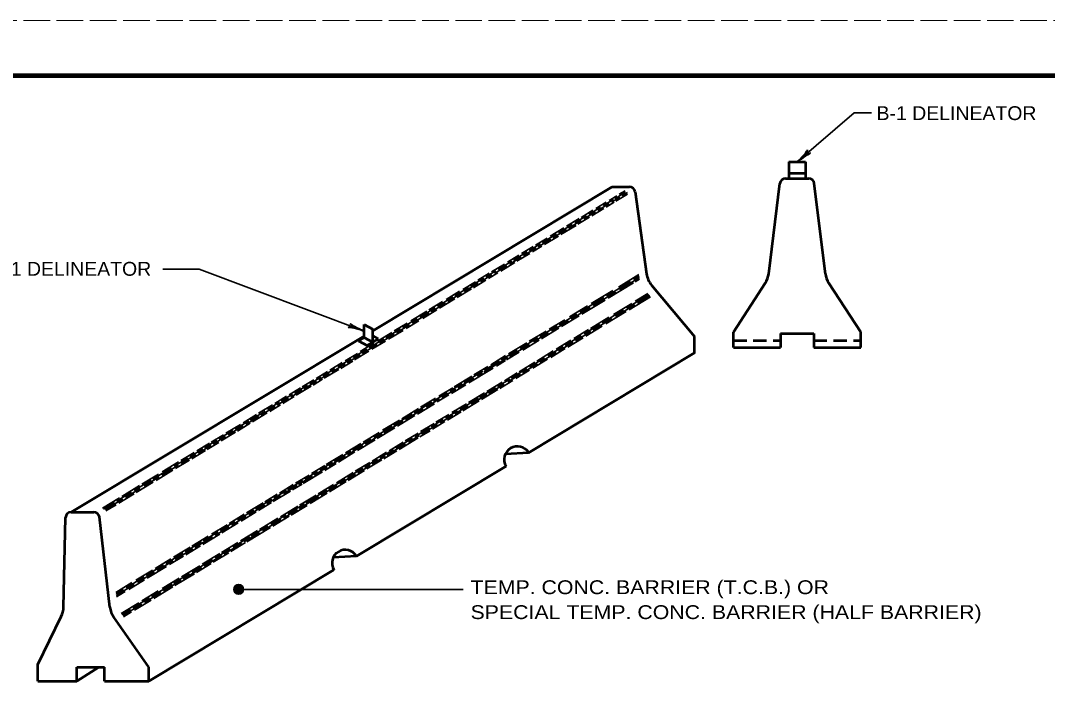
# Model space of a CAD drawing. Extents: x -60 to 620, y -42 to 398.
# Drawn here: x 155.3 to 340.7, y 276.6 to 398.3 of the extents above; entities that cross this region are included whole.
import ezdxf

# ---------------------------------------------------------------- set-up
doc = ezdxf.new("R2010")
doc.units = 0
doc.header["$LTSCALE"] = 0.8
doc.linetypes.add('LONG_DASHED', pattern=[7.5, 6, -1.5])
doc.linetypes.add('MEDIUM_DASHED', pattern=[4.5, 3, -1.5])
doc.layers.add('1', color=7, linetype='Continuous', lineweight=35)
doc.layers.add('61', color=7, linetype='Continuous', lineweight=35)

msp = doc.modelspace()

# ---------------------------------------------------------------- hatches: boundary and pattern name
at = {"layer": '1'}
msp.add_hatch(color=256, dxfattribs=at).paths.add_polyline_path([(195.5118, 295.5681, 1), (193.7618, 295.5681, 1)])

# ---------------------------------------------------------------- linework, layer by layer
for p, q in [((295.478, 372.7356), (305.7999, 381.5928)), ((305.7999, 381.5928), (308.9546, 381.5928)), ((262.5535, 366.1046), (264.5031, 367.2884)), ((263.3894, 366.9047), (264.4197, 367.5302)), ((263.9162, 366.6396), (264.8951, 367.2339)), ((259.1647, 364.3393), (261.0014, 365.4547)), ((260.4839, 364.8479), (262.3297, 365.9687)), ((260.9856, 364.5675), (262.4392, 365.4502)), ((261.5572, 365.7921), (262.9602, 366.644)), ((261.969, 365.4572), (263.4574, 366.361)), ((262.753, 365.6407), (264.8434, 366.9101)), ((256.4974, 362.7197), (258.6156, 364.0059)), ((256.9967, 362.4379), (259.0848, 363.7058)), ((257.872, 363.2619), (260.0132, 364.5621)), ((258.4358, 363.0192), (260.5839, 364.3236)), ((259.505, 363.961), (261.5747, 365.2177)), ((253.8622, 361.1196), (256.1582, 362.5138)), ((254.221, 360.7525), (256.5235, 362.1506)), ((255.3568, 361.7346), (257.4518, 363.0068)), ((255.9095, 361.4853), (258.0276, 362.7714)), ((250.8938, 359.3171), (253.387, 360.831)), ((251.4117, 359.0467), (253.8287, 360.5143)), ((252.3987, 359.9384), (254.8791, 361.4445)), ((252.8405, 359.6217), (255.5677, 361.2777)), ((247.1182, 356.7321), (249.1432, 357.9617)), ((248.2676, 357.7223), (250.3784, 359.0041)), ((248.7187, 357.4115), (251.0367, 358.819)), ((249.4825, 358.1677), (252.0295, 359.7142)), ((249.8741, 357.8205), (252.3858, 359.3457)), ((244.285, 355.0117), (246.737, 356.5006)), ((244.888, 354.7928), (247.2346, 356.2177)), ((245.7516, 356.1946), (247.8228, 357.4522)), ((246.0662, 355.8009), (248.3838, 357.2082)), ((247.7393, 356.5242), (249.4137, 357.5409)), ((240.3007, 352.8847), (242.6382, 354.3041)), ((241.4888, 353.3137), (244.0006, 354.8389)), ((241.975, 353.024), (244.531, 354.5761)), ((243.1803, 354.6332), (245.2448, 355.8869)), ((243.5564, 354.2769), (245.6607, 355.5546)), ((187.4968, 353.386), (180.9689, 353.386)), ((217.2972, 342.2008), (187.4968, 353.386)), ((237.8245, 351.3812), (239.8977, 352.64)), ((238.2916, 351.08), (240.3693, 352.3417)), ((239.2987, 351.9838), (241.1162, 353.0875)), ((239.7539, 351.6753), (241.4659, 352.7149)), ((240.8224, 352.6167), (243.0474, 353.9677)), ((263.232, 350.1377), (266.9404, 352.3895)), ((235.1097, 349.7328), (237.388, 351.1162)), ((235.3907, 349.3186), (237.9051, 350.8453)), ((236.5147, 350.2933), (238.9479, 351.7708)), ((237.0272, 350.0196), (239.26, 351.3754)), ((261.0687, 348.5315), (265.3803, 351.1496)), ((261.3697, 348.1295), (265.9254, 350.8957)), ((263.4035, 349.6568), (267.0162, 351.8505)), ((265.9788, 351.513), (266.9783, 352.1199)), ((266.2675, 351.1035), (267.0575, 351.5832)), ((232.1138, 347.9136), (234.542, 349.388)), ((232.4254, 347.518), (234.916, 349.0302)), ((233.6831, 348.574), (236.1639, 350.0804)), ((234.1358, 348.2638), (236.7147, 349.8297)), ((258.3218, 347.1562), (262.2188, 349.5224)), ((258.6832, 346.7906), (262.7323, 349.2492)), ((264.7004, 346.3497), (268.7215, 348.7912)), ((266.2342, 347.5735), (268.5589, 348.9851)), ((228.9977, 346.0214), (231.4598, 347.5165)), ((229.4239, 345.6954), (231.9935, 347.2557)), ((230.5411, 346.6662), (233.3391, 348.3652)), ((230.9339, 346.3196), (233.7132, 348.0072)), ((256.2758, 345.6212), (260.5806, 348.2352)), ((256.5926, 345.2287), (260.8157, 347.7931)), ((262.3368, 345.2069), (265.6262, 347.2043)), ((262.7146, 344.8512), (266.1714, 346.9502)), ((265.1914, 346.0628), (269.0465, 348.4037)), ((266.6622, 347.2483), (268.884, 348.5974)), ((225.7531, 344.0512), (228.6448, 345.8072)), ((225.9983, 343.6153), (229.0236, 345.4522)), ((227.337, 344.7207), (230.1376, 346.4212)), ((227.9065, 344.4813), (230.4425, 346.0213)), ((252.5252, 343.3438), (255.7178, 345.2823)), ((252.9456, 343.0143), (256.1078, 344.9344)), ((254.3836, 344.7648), (257.6726, 346.7619)), ((254.6943, 344.3684), (258.1006, 346.4367)), ((260.3031, 343.6795), (264.1527, 346.017)), ((260.9339, 343.4776), (264.6217, 345.7169)), ((222.7478, 342.2264), (225.0788, 343.6418)), ((223.1743, 341.9006), (225.4858, 343.3042)), ((224.2084, 342.8209), (226.8839, 344.4455)), ((224.8757, 342.641), (227.2127, 344.06)), ((249.0377, 341.2261), (252.181, 343.1347)), ((250.733, 342.5481), (253.521, 344.241)), ((251.1176, 342.1966), (254.1992, 344.0677)), ((257.0314, 341.6928), (259.8534, 343.4064)), ((257.3536, 341.3036), (260.3005, 343.093)), ((258.1724, 342.6782), (261.4882, 344.6916)), ((258.6314, 342.3719), (262.0525, 344.4493)), ((219.6967, 340.3737), (222.3256, 341.97)), ((220.0681, 340.0144), (222.745, 341.6398)), ((221.2198, 341.0062), (223.875, 342.6184)), ((221.7079, 340.7174), (224.3632, 342.3297)), ((247.1119, 340.3493), (250.1517, 342.1952)), ((247.8792, 340.2303), (250.6076, 341.8869)), ((249.3361, 340.8225), (252.462, 342.7206)), ((253.6152, 339.6184), (256.5247, 341.3851)), ((255.1737, 340.8574), (257.8075, 342.4567)), ((255.4638, 340.4485), (258.2666, 342.1504)), ((216.5927, 338.4889), (219.0722, 339.9945)), ((216.9714, 338.1341), (219.6438, 339.7568)), ((218.1878, 339.1651), (220.843, 340.7773)), ((218.724, 338.9055), (221.1882, 340.4018)), ((243.3826, 338.0848), (246.6817, 340.0881)), ((243.5617, 337.6087), (247.1406, 339.7818)), ((245.5085, 339.0831), (248.6697, 341.0027)), ((245.9583, 338.7715), (248.9, 340.5577)), ((250.4776, 337.7133), (253.2767, 339.4129)), ((251.9591, 338.9055), (254.6432, 340.5352)), ((252.3912, 338.5828), (255.0457, 340.1947)), ((254.0768, 339.3138), (256.85, 340.9977)), ((213.8655, 336.833), (216.0838, 338.18)), ((214.2623, 336.4891), (216.5843, 337.899)), ((215.3446, 337.4387), (217.8157, 338.9392)), ((215.554, 336.9807), (218.1613, 338.5639)), ((240.159, 336.1274), (242.8564, 337.7653)), ((242.0493, 336.9827), (244.9716, 338.7571)), ((243.0447, 337.0023), (245.3085, 338.3769)), ((248.4837, 336.7952), (251.4697, 338.6083)), ((249.0481, 336.5528), (251.9937, 338.3414)), ((251.0042, 337.4482), (253.6111, 339.0312)), ((211.1238, 335.1683), (213.3567, 336.5241)), ((211.4899, 334.8056), (213.9052, 336.2722)), ((212.5755, 335.7572), (214.9674, 337.2097)), ((213.0705, 335.4727), (215.2408, 336.7905)), ((237.1254, 334.2854), (239.6424, 335.8137)), ((238.9225, 334.7917), (243.2472, 337.4178)), ((238.9693, 335.1125), (241.7348, 336.7917)), ((241.2, 335.8822), (242.8521, 336.8853)), ((245.2943, 334.8586), (248.1232, 336.5763)), ((245.9268, 334.6576), (248.6169, 336.291)), ((247.1409, 335.6872), (249.8901, 337.3565)), ((247.7681, 335.4832), (250.4467, 337.1096)), ((207.4997, 332.6751), (209.4758, 333.875)), ((208.6469, 333.6642), (210.6885, 334.9039)), ((209.1493, 333.3843), (211.0607, 334.5449)), ((209.8596, 334.1081), (212.007, 335.412)), ((210.105, 333.672), (212.7391, 335.2715)), ((233.5897, 332.1384), (236.7477, 334.056)), ((235.3289, 332.902), (238.7377, 334.9718)), ((236.2368, 332.8684), (240.5789, 335.505)), ((237.714, 334.0578), (238.6639, 334.6347)), ((242.6265, 333.2386), (244.9704, 334.6618)), ((243.2632, 333.0403), (245.52, 334.4106)), ((243.8514, 333.6898), (246.6997, 335.4193)), ((244.7198, 333.6322), (247.1982, 335.1371)), ((203.7519, 330.6919), (205.7999, 331.9355)), ((204.7315, 330.9942), (207.0978, 332.4311)), ((205.0442, 330.599), (207.7327, 332.2315)), ((206.1482, 332.147), (208.2352, 333.4142)), ((206.433, 331.7349), (208.732, 333.1309)), ((208.093, 332.4502), (209.8141, 333.4953)), ((230.768, 330.4251), (233.2981, 331.9614)), ((232.7685, 331.3473), (235.0339, 332.7229)), ((233.0629, 330.9412), (235.6689, 332.5237)), ((234.2262, 331.94), (237.1146, 333.6938)), ((238.1547, 330.2306), (241.0491, 331.9881)), ((239.4637, 331.3181), (242.2218, 332.9928)), ((239.7842, 330.9277), (242.6009, 332.6381)), ((241.4147, 332.2101), (243.5956, 333.5343)), ((241.7963, 331.8571), (244.145, 333.2833)), ((201.1731, 329.126), (203.3187, 330.4289)), ((202.3236, 329.5321), (204.4012, 330.7937)), ((202.6084, 329.12), (204.6602, 330.3659)), ((204.0487, 330.2872), (206.1142, 331.5414)), ((229.8422, 329.5704), (232.3301, 331.0811)), ((230.5155, 329.3944), (232.6045, 330.6629)), ((231.3541, 330.196), (233.8495, 331.7113)), ((234.5898, 328.0659), (237.9595, 330.1121)), ((236.1646, 329.3148), (239.0663, 331.0768)), ((236.6604, 329.0309), (239.5088, 330.7605)), ((238.5312, 329.8744), (241.4745, 331.6617)), ((198.2565, 327.355), (200.7399, 328.863)), ((198.669, 327.0206), (201.2284, 328.5747)), ((199.8316, 328.0189), (202.0169, 329.3458)), ((200.2532, 327.6899), (202.2246, 328.887)), ((201.5924, 328.7957), (203.6747, 330.0601)), ((224.0927, 326.3717), (227.1535, 328.2303)), ((226.3399, 327.4437), (229.5356, 329.3842)), ((226.9409, 327.2238), (230.007, 329.0856)), ((227.485, 328.4316), (230.1823, 330.0694)), ((228.5077, 328.4676), (230.9405, 329.9448)), ((233.1579, 327.4891), (235.7768, 329.0793)), ((233.7147, 327.2422), (236.0853, 328.6817)), ((235.1367, 327.8132), (238.1096, 329.6184)), ((195.4571, 325.6552), (197.8735, 327.1225)), ((195.9205, 325.3517), (198.2906, 326.7908)), ((196.7383, 326.1407), (199.409, 327.7623)), ((197.1595, 325.8113), (199.8092, 327.4203)), ((222.6184, 325.184), (225.9733, 327.2212)), ((223.3317, 325.0322), (226.4821, 326.9452)), ((224.7786, 326.2032), (227.9592, 328.1346)), ((230.2742, 325.738), (232.5899, 327.1442)), ((231.0248, 325.6088), (233.298, 326.9892)), ((232.0027, 326.495), (234.1387, 327.7921)), ((232.3872, 326.1437), (234.8196, 327.6207)), ((192.3152, 323.7473), (194.9734, 325.3615)), ((192.7722, 323.44), (195.4724, 325.0796)), ((194.0317, 324.4972), (196.4647, 325.9745)), ((194.4361, 324.1577), (196.7556, 325.5661)), ((219.0434, 323.0132), (222.354, 325.0235)), ((219.6735, 322.8109), (222.8454, 324.737)), ((220.6516, 324.2822), (223.6987, 326.1325)), ((220.8912, 323.8428), (224.3446, 325.9398)), ((226.4402, 323.1174), (229.0866, 324.7242)), ((227.4759, 324.0388), (229.9326, 325.5306)), ((227.6473, 323.5579), (230.5514, 325.3213)), ((229.4007, 324.9151), (231.5967, 326.2485)), ((229.66, 324.4878), (231.8986, 325.8471)), ((189.6807, 322.1477), (191.8985, 323.4943)), ((190.0524, 321.7885), (192.2972, 323.1515)), ((191.0999, 322.7169), (193.5941, 324.2314)), ((191.4762, 322.3604), (194.0827, 323.9431)), ((215.1992, 320.6789), (218.5341, 322.7039)), ((217.1377, 322.1486), (220.014, 323.8951)), ((217.4882, 321.7764), (220.5435, 323.6317)), ((223.0268, 321.0447), (226.0593, 322.8862)), ((223.6093, 320.8137), (227.0904, 322.9275)), ((224.7234, 322.3675), (227.0751, 323.7955)), ((225.2983, 322.1316), (227.3274, 323.3637)), ((227.3678, 323.0959), (229.2039, 324.2107)), ((185.8041, 319.5012), (188.1863, 320.9477)), ((187.1022, 320.5819), (189.3657, 321.9563)), ((187.3518, 320.1487), (189.6643, 321.5528)), ((188.4692, 321.1195), (190.7266, 322.4903)), ((188.9695, 320.8383), (191.0537, 322.1038)), ((213.9239, 320.1972), (216.7091, 321.8883)), ((214.2793, 319.828), (217.0973, 321.5391)), ((216.1093, 320.6467), (219.288, 322.5768)), ((220.1352, 319.2889), (222.636, 320.8074)), ((221.4334, 319.7847), (224.7939, 321.8252)), ((221.8116, 320.5994), (224.3477, 322.1394)), ((182.9983, 317.7976), (185.4441, 319.2827)), ((184.1859, 318.8112), (186.6047, 320.2798)), ((184.2712, 318.278), (186.9408, 319.8991)), ((186.1726, 319.1399), (188.6471, 320.6425)), ((210.4693, 318.0995), (213.4572, 319.9137)), ((210.9169, 317.7862), (213.9437, 319.6242)), ((211.9069, 318.6798), (214.9242, 320.5119)), ((212.6558, 318.5497), (215.6578, 320.3726)), ((217.403, 317.6298), (219.7394, 319.0486)), ((218.7337, 318.7305), (221.3705, 320.3316)), ((218.7464, 318.1532), (221.1637, 319.621)), ((220.8891, 319.1619), (223.2359, 320.5869)), ((179.1759, 315.4766), (182.4957, 317.4923)), ((180.7889, 316.1635), (183.7914, 317.9867)), ((180.8427, 316.7811), (183.8086, 318.5821)), ((183.2684, 317.3765), (185.7955, 318.911)), ((207.8038, 316.481), (210.2237, 317.9504)), ((208.2956, 316.1946), (210.6408, 317.6187)), ((209.2843, 317.0873), (211.6192, 318.5052)), ((210.1901, 317.0524), (212.2623, 318.3107)), ((214.3148, 315.7547), (217.0902, 317.4399)), ((215.6887, 316.8815), (218.3227, 318.4809)), ((216.1425, 316.572), (218.4086, 317.948)), ((217.8212, 317.299), (220.5086, 318.9308)), ((175.7732, 313.4104), (178.8216, 315.2614)), ((177.1662, 314.5487), (180.1981, 316.3897)), ((177.5681, 314.2077), (180.3162, 315.8765)), ((179.7303, 315.2282), (182.7858, 317.0835)), ((204.9177, 314.7285), (207.3569, 316.2096)), ((205.4728, 314.4806), (207.9808, 316.0034)), ((206.3272, 314.7067), (209.779, 316.8028)), ((206.5721, 315.4404), (208.8678, 316.8344)), ((210.8715, 313.6638), (213.8562, 315.4762)), ((212.307, 314.8281), (215.3055, 316.6488)), ((212.9094, 314.6088), (215.7593, 316.3393)), ((214.4436, 315.2481), (217.3801, 317.0312)), ((173.5387, 312.346), (176.7524, 314.2974)), ((174.2054, 312.1658), (176.8771, 313.7882)), ((176.1398, 313.048), (179.2412, 314.9312)), ((200.9901, 312.051), (203.2637, 313.4316)), ((201.9958, 312.9543), (204.4983, 314.4738)), ((202.7577, 312.8319), (205.2327, 314.3347)), ((203.4901, 313.569), (206.219, 315.226)), ((204.3738, 313.5206), (206.1312, 314.5877)), ((206.7851, 311.1825), (210.5871, 313.4912)), ((209.0349, 312.8413), (211.7525, 314.4914)), ((209.5154, 312.5479), (212.4678, 314.3407)), ((211.0704, 313.1998), (214.0904, 315.0337)), ((170.0911, 310.2526), (173.1549, 312.113)), ((170.5647, 309.9552), (173.7192, 311.8707)), ((172.5623, 311.4607), (175.3135, 313.1313)), ((172.9884, 311.1344), (175.756, 312.8149)), ((197.6959, 310.0507), (200.6286, 311.8314)), ((199.3746, 311.3626), (201.626, 312.7297)), ((199.7474, 311.004), (202.1895, 312.4869)), ((200.8861, 311.4028), (204.0093, 313.2993)), ((205.5945, 310.1671), (209.1014, 312.2965)), ((205.6356, 310.7772), (208.6346, 312.5983)), ((207.5439, 311.0585), (210.6456, 312.9418)), ((170.2418, 310.0517), (172.2351, 311.262)), ((170.6658, 309.7241), (172.5023, 310.8392)), ((194.4237, 308.0637), (197.4115, 309.8779)), ((196.0798, 309.362), (199.0459, 311.1631)), ((196.4823, 309.0214), (199.3609, 310.7693)), ((198.2372, 309.7944), (200.6101, 311.2353)), ((202.1945, 308.6877), (205.3237, 310.5877)), ((202.7198, 308.4216), (205.2827, 309.9778)), ((203.5375, 309.2105), (206.5448, 311.0366)), ((204.1254, 308.9828), (206.9977, 310.7268)), ((192.9445, 307.4582), (195.6687, 309.1123)), ((193.3651, 307.1286), (196.0185, 308.7398)), ((195.0825, 307.8788), (197.8094, 309.5347)), ((198.4253, 306.399), (201.7255, 308.4029)), ((198.9752, 306.1477), (202.2974, 308.1651)), ((200.4442, 307.3322), (203.1898, 308.9993)), ((200.8337, 306.9839), (203.7586, 308.7599)), ((189.7345, 305.509), (192.5602, 307.2247)), ((190.3798, 305.3159), (192.9367, 306.8685)), ((191.3286, 306.1843), (193.9695, 307.7879)), ((191.5989, 305.7636), (194.5441, 307.5519)), ((194.9963, 304.3168), (198.0806, 306.1897)), ((196.1402, 304.1339), (200.4089, 306.7259)), ((196.8793, 305.1676), (199.9392, 307.0256)), ((184.9928, 302.3371), (187.9417, 304.1277)), ((186.2109, 303.3695), (189.1732, 305.1683)), ((186.7635, 303.12), (189.9381, 305.0477)), ((188.1681, 303.6803), (191.25, 305.5517)), ((188.2554, 304.3182), (190.9403, 305.9486)), ((193.5839, 303.1666), (196.6392, 305.0218)), ((195.6684, 304.1398), (198.4314, 305.8176)), ((182.8901, 301.353), (185.8839, 303.1709)), ((183.1606, 300.9323), (186.3572, 302.8732)), ((185.1082, 301.8223), (187.7837, 303.447)), ((190.3873, 301.2256), (193.1382, 302.896)), ((191.5788, 302.2417), (194.5153, 304.0247)), ((191.9956, 301.9097), (195.2227, 303.8692)), ((193.2625, 302.3866), (195.9137, 303.9964)), ((179.574, 299.3394), (182.4043, 301.0581)), ((179.9065, 298.9563), (182.7982, 300.7122)), ((181.4864, 300.208), (184.6303, 302.1171)), ((182.1718, 300.0392), (184.7067, 301.5784)), ((186.2239, 298.6975), (189.9016, 300.9307)), ((188.0427, 300.0945), (191.2432, 302.0378)), ((188.4366, 299.7486), (191.6112, 301.6762)), ((190.0706, 300.4484), (192.8742, 302.1508)), ((176.0599, 297.2056), (179.0796, 299.0392)), ((176.3877, 296.8197), (179.4601, 298.6852)), ((177.9542, 298.0632), (181.0887, 299.9665)), ((178.1452, 297.5942), (181.6421, 299.7176)), ((184.3155, 297.8313), (187.6229, 299.8396)), ((184.6213, 297.4319), (187.9815, 299.4722)), ((187.0595, 298.62), (189.713, 300.2312)), ((172.4714, 295.0266), (175.3658, 296.7841)), ((174.3158, 295.8539), (177.5832, 297.8379)), ((174.8071, 295.5673), (177.6461, 297.2912)), ((180.8407, 295.7212), (183.9092, 297.5845)), ((181.049, 295.2627), (184.2723, 297.22)), ((182.8858, 296.6706), (185.7602, 298.4159)), ((183.1467, 296.2442), (186.6532, 298.3732)), ((172.5033, 294.7533), (173.834, 295.5613)), ((172.5351, 294.4803), (175.7997, 296.4626)), ((172.5669, 294.2071), (174.1665, 295.1783)), ((177.1842, 293.501), (180.1387, 295.2951)), ((177.6582, 293.2038), (180.612, 294.9974)), ((178.9378, 294.2732), (182.6163, 296.5068)), ((179.3229, 293.9222), (182.7939, 296.0298)), ((194.6368, 295.5681), (235.1641, 295.5681)), ((173.4386, 291.2267), (176.5971, 293.1445)), ((175.5557, 292.2196), (178.5716, 294.0508)), ((175.8261, 291.7989), (178.8286, 293.6221)), ((173.5823, 291.0213), (175.114, 291.9514)), ((173.726, 290.8162), (177.1677, 292.9061)), ((173.8697, 290.6109), (175.305, 291.4825))]:
    msp.add_line(p, q, dxfattribs=at)
at = {"layer": '1', "lineweight": 53}
for p, q in [((293.978, 372.7356), (293.978, 369.7356)), ((293.978, 372.7356), (296.978, 372.7356)), ((296.978, 372.7356), (296.978, 369.7356)), ((293.3687, 369.7462), (297.6005, 369.7462)), ((293.978, 370.7356), (296.978, 370.7356)), ((218.8597, 342.2463), (262.1055, 368.2311)), ((262.1057, 368.2311), (265.2364, 368.2311)), ((266.2267, 367.3702), (268.312, 352.5318)), ((290.3609, 352.5558), (292.3762, 368.8687)), ((300.6082, 352.5558), (298.593, 368.8687)), ((269.2083, 350.5181), (276.9846, 341.2462)), ((283.9846, 341.9962), (289.7458, 350.8678)), ((306.9846, 341.9962), (301.2233, 350.8678)), ((217.2972, 341.0289), (217.2972, 343.3727)), ((217.2972, 343.3727), (218.8597, 342.5317)), ((164.3886, 309.5168), (217.2972, 341.3075)), ((218.8597, 340.188), (218.8597, 342.5317)), ((218.8597, 341.3478), (219.856, 340.8057)), ((283.9846, 339.2462), (283.9846, 341.9962)), ((292.4846, 341.7462), (292.4846, 339.2462)), ((292.4846, 341.7462), (298.4846, 341.7462)), ((298.4846, 341.7462), (298.4846, 339.2462)), ((306.9846, 339.2462), (306.9846, 341.9962)), ((216.2926, 340.4253), (217.2972, 341.0289)), ((216.2926, 340.4253), (217.8637, 339.5702)), ((217.2972, 341.0289), (218.8597, 340.188)), ((217.858, 339.5797), (218.8597, 340.188)), ((218.8542, 340.1973), (219.856, 340.8057)), ((283.9846, 339.2462), (292.4846, 339.2462)), ((298.4846, 339.2462), (306.9846, 339.2462)), ((247.0161, 320.2392), (242.8072, 319.9917)), ((215.9276, 301.5593), (242.9283, 317.783)), ((163.0325, 292.3312), (163.3888, 308.5387)), ((164.3886, 309.5168), (168.5201, 309.5168)), ((171.4105, 292.3503), (169.5133, 308.6325)), ((215.9276, 301.5593), (211.7187, 301.3119)), ((211.8398, 299.1032), (178.4103, 279.0168)), ((158.4103, 282.0168), (162.6287, 290.6656)), ((178.4103, 281.5168), (172.107, 290.5188)), ((158.4103, 279.0168), (158.4103, 282.0168)), ((165.4103, 279.0168), (165.4103, 281.5168)), ((165.4103, 281.5168), (170.4103, 281.5168)), ((165.4103, 279.0168), (169.4103, 281.5168)), ((170.4103, 279.0168), (170.4103, 281.5168)), ((178.4103, 279.0168), (178.4103, 281.5168)), ((158.4103, 279.0168), (165.4103, 279.0168)), ((170.4103, 279.0168), (178.4103, 279.0168))]:
    msp.add_line(p, q, dxfattribs=at)
at = {"layer": '1', "linetype": 'MEDIUM_DASHED', "lineweight": 53}
for p, q in [((283.9846, 340.4962), (292.4846, 340.4962)), ((298.4846, 340.4962), (306.9846, 340.4962))]:
    msp.add_line(p, q, dxfattribs=at)
at = {"layer": '1', "lineweight": 53}
msp.add_lwpolyline([(247.0161, 320.2392), (276.9846, 338.2462), (276.9846, 341.2462)], dxfattribs=at)
at = {"layer": '1'}
msp.add_circle((194.6368, 295.5681), 0.875, dxfattribs=at)
at = {"layer": '1', "lineweight": 53}
for centre, radius, start, end in [((293.3686, 368.7462), 1, 90, 172.95699), ((297.6005, 368.7462), 1, 7.04303, 90), ((265.2364, 367.2311), 1, 8.00018, 90), ((272.2731, 353.0885), 4, 188.00017, 219.98679), ((286.3911, 353.0463), 4, 327.00063, 352.95779), ((304.578, 353.0463), 4, 187.04242, 212.99913), ((244.977, 319.0031), 2.3845, 31.22371, 210.77626), ((164.3886, 308.5168), 1, 90, 178.73944), ((168.5201, 308.5168), 1, 6.64453, 90), ((213.8885, 300.3233), 2.3845, 31.22371, 210.77626), ((159.0335, 292.4191), 4, 333.99969, 358.74001), ((175.3836, 292.8131), 4, 186.64528, 214.99909)]:
    msp.add_arc(centre, radius, start, end, dxfattribs=at)
at = {"layer": '1', "lineweight": 40}
for centre, major_axis, ratio, start_param, end_param in [((296.1262, 373.6559), (-1.2535, -1.2814), 0.122415, 0.89635335, 3.14159265), ((296.4661, 373.3047), (-1.4473, -1.0105), 0.07063, 3.14071475, 5.41810995), ((216.3226, 342.7927), (1.5827, -0.7817), 0.07063, 3.14071475, 5.41810995), ((216.1785, 342.3256), (1.7267, -0.4813), 0.122415, 0.89635335, 3.14159265)]:
    msp.add_ellipse(centre, major_axis=major_axis, ratio=ratio, start_param=start_param, end_param=end_param, dxfattribs=at)
at = {"layer": '61', "linetype": 'LONG_DASHED', "lineweight": 13}
msp.add_line((-60.2155, 398.2688), (619.8045, 398.2688), dxfattribs=at)
at = {"layer": '61', "lineweight": 158}
msp.add_lwpolyline([(608.8245, 388.2688), (-30.2155, 388.2688), (-30.2155, -31.7512)], dxfattribs=at)

# ---------------------------------------------------------------- texts
at = {"layer": '1'}
for s, width, p in [('B-1 DELINEATOR', 1.05, (309.8401, 380.2976)), ('B-1 DELINEATOR', 1.05, (149.9911, 352.1882)), ('TEMP. CONC. BARRIER (T.C.B.) OR', 1.15, (236.5241, 294.7006)), ('SPECIAL TEMP. CONC. BARRIER (HALF BARRIER)', 1.15, (236.5241, 290.2006))]:
    msp.add_text(s, height=2.5, dxfattribs=dict(at, width=width)).set_placement(p)

doc.saveas('drawing.dxf')
